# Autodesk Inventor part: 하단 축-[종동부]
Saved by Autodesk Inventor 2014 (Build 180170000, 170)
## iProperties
Created: 2025-02
Part Number: 하단 축-[종동부]
Material: 강철, 탄소
Document SubType Name: Modeling
Designer: dg
Density: 7.87 g/cm^3
Appearance: 반연마
Mass: 53.6272 g
Surface Area: 29.2714 cm^2
Volume: 6.81413 cm^3
Author: jhkim
Creation Date: 2025-01-06
Sending System: Autodesk Inventor 2025
Preprocessor: ST-DEVELOPER v20
Author: dg
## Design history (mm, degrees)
node "하단 축1"
node "솔리드1"
node "기준1"
